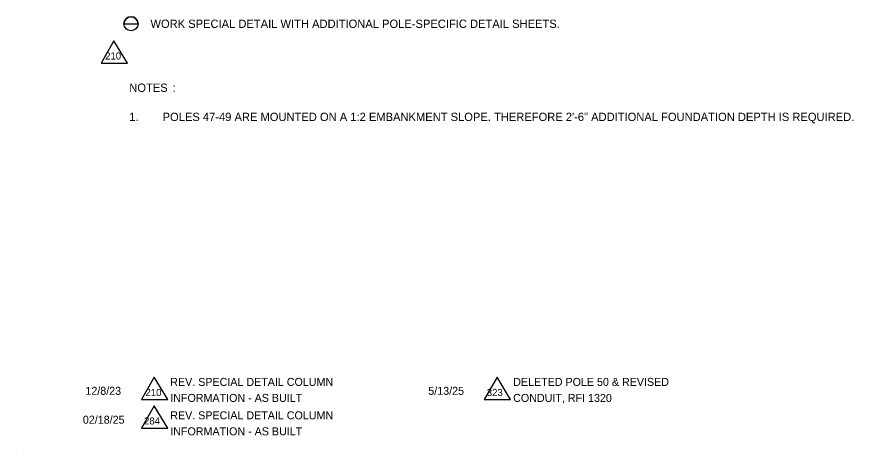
# Model space of a CAD drawing. Extents: x -816.7 to -800.7, y -2197.9 to -2187.9.
# Drawn here: x -816.67 to -809.64, y -2197.9 to -2194.23 of the extents above; entities that cross this region are included whole.
import ezdxf

# ---------------------------------------------------------------- set-up
doc = ezdxf.new("R2010")
doc.units = 0
for name, color, linetype in [('AdhocPoint_dp', 7, 'Continuous'), ('Cloud_dp', 7, 'Continuous'), ('TextLabel', 7, 'Continuous'), ('TextMinor', 7, 'Continuous')]:
    doc.layers.add(name, color=color, linetype=linetype)

msp = doc.modelspace()

# ---------------------------------------------------------------- linework, layer by layer
at = {"layer": 'AdhocPoint_dp'}
msp.add_line((-816.6686, -2197.8985), (-816.6686, -2197.8985), dxfattribs=at)
at = {"layer": 'Cloud_dp'}
for points in [[(-815.8525, -2194.4323), (-815.9603, -2194.6204), (-815.7396, -2194.6204)], [(-815.5137, -2197.2596), (-815.6215, -2197.4477), (-815.4008, -2197.4477)], [(-812.6337, -2197.2596), (-812.7415, -2197.4477), (-812.5208, -2197.4477)], [(-815.5137, -2197.4986), (-815.6215, -2197.6867), (-815.4008, -2197.6867)]]:
    msp.add_lwpolyline(points, close=True, dxfattribs=at)
at = {"layer": 'TextLabel'}
msp.add_line((-815.7681, -2194.2899), (-815.6496, -2194.2899), dxfattribs=at)
msp.add_line((-815.7681, -2194.2899), (-815.6496, -2194.2899), dxfattribs=at)
msp.add_circle((-815.7089, -2194.2899), 0.0593, dxfattribs=at)
msp.add_arc((-815.7089, -2194.2899), 0.0593, 0, 180, dxfattribs=at)

# ---------------------------------------------------------------- texts
at = {"layer": 'Cloud_dp'}
for s, p in [('210', (-815.9258, -2194.5903)), ('210', (-815.587, -2197.4175)), ('323', (-812.7205, -2197.4175)), ('284', (-815.5991, -2197.6565))]:
    msp.add_text(s, height=0.05998, rotation=0, dxfattribs=at).set_placement(p)
at = {"layer": 'TextLabel'}
for s, p in [('WORK SPECIAL DETAIL WITH ADDITIONAL POLE-SPECIFIC DETAIL SHEETS.', (-815.5457, -2194.3249)), ('NOTES', (-815.7233, -2194.8621)), (':', (-815.3599, -2194.8621)), ('1.', (-815.7233, -2195.1071)), ('POLES 47-49 ARE MOUNTED ON A 1:2 EMBANKMENT SLOPE. THEREFORE 2\'-6" ADDITIONAL FOUNDATION DEPTH IS REQUIRED.', (-815.4433, -2195.1071))]:
    msp.add_text(s, height=0.07, dxfattribs=at).set_placement(p)
at = {"layer": 'TextMinor'}
for s, p in [('REV. SPECIAL DETAIL COLUMN ', (-815.3793, -2197.3326)), ('DELETED POLE 50 & REVISED ', (-812.4993, -2197.3326)), ('12/8/23', (-816.0919, -2197.4075)), ('5/13/25', (-813.2119, -2197.4075)), ('INFORMATION - AS BUILT', (-815.3793, -2197.467)), ('CONDUIT, RFI 1320', (-812.4993, -2197.467)), ('REV. SPECIAL DETAIL COLUMN ', (-815.3793, -2197.6132)), ('02/18/25', (-816.1129, -2197.6501)), ('INFORMATION - AS BUILT', (-815.3793, -2197.7476))]:
    msp.add_text(s, height=0.0672, rotation=360, dxfattribs=at).set_placement(p)

doc.saveas('drawing.dxf')
